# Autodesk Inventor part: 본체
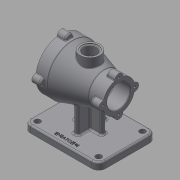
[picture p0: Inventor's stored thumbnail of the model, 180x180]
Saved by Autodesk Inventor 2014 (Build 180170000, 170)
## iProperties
Created: 2020-12
Part Number: 본체
Material: Generic
Document SubType Name: Modeling
Designer: kh
Density: 1 g/cm^3
Appearance: Default
Author: kh
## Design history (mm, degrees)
sketch "스케치1"
  geometry: L1 (-65, 50)-(65, 50); L2 (65, 50)-(65, -50); L3 (65, -50)-(-65, -50); L4 (-65, -50)-(-65, 50); L5 (-65, 50)-(65, -50); L6 (65, 50)-(-65, -50); 1 further point
  constraints: 12 end point, 2 midpoint, 2 parallel, 1 horizontal, 1 perpendicular
  dimensions: "d0" = 130 distance between parallel lines of L2 L4; "d1" = 100 distance between parallel lines of L3 L1
extrude "돌출1" new body sketch "스케치1" distance "d2" = 12; taper "d3" = 0 deg
sketch "스케치2"
  geometry: L1 (50, 82)-(-50, 82); L2 (-50, 82)-(-50, 109.5); L3 (-50, 109.5)-(-25, 109.5); L4 (-25, 109.5)-(30, 126); L5 (30, 126)-(50, 126); L6 (50, 126)-(50, 82); 2 further points
  constraints: 12 end point, 3 parallel, 1 horizontal, 1 midpoint, 1 perpendicular, 1 vertical alignment
  dimensions: "d4" = 82 distance from line of point (0, 0) L1; "d5" = 100 distance between parallel lines of L2 L6; "d6" = 55 diameter of L3 L1; "d7" = 88 diameter of L5 L1; "d8" = 20 distance of L4.end L5.end; "d119" = 25 distance of L2.end L3.end
revolve "회전1" sketch "스케치2" stored, may be unused: angle "d9" = 90 deg
sketch "스케치3"
  geometry: L1 (-24, 74.215)-(24, 74.215); L2 (24, 74.215)-(24, 0); L3 (24, 0)-(-24, 0); L4 (-24, 0)-(-24, 74.215); L5 (-24, 74.215)-(24, 0); L6 (24, 74.215)-(-24, 0); L7 (-65, 0)-(65, 0) reference; 4 further points
  constraints: 12 end point, 5 midpoint, 2 parallel, 1 horizontal, 1 perpendicular, 1 vertical alignment
  dimensions: "d10" = 48 distance between parallel lines of L2 L4
extrude "돌출2" join sketch "스케치3" stored distance "d11" = 8; taper "d12" = 0 deg
sketch "스케치4"
  geometry: L1 (-25, 90.309)-(25, 90.309); L2 (25, 90.309)-(25, 0); L3 (25, 0)-(-25, 0); L4 (-25, 0)-(-25, 90.309); 2 further points
  constraints: 8 end point, 2 parallel, 1 coincident, 1 horizontal, 1 midpoint, 1 perpendicular
  dimensions: "d120" = 50 distance between parallel lines of L4 L2
extrude "돌출3" join sketch "스케치4" stored distance "d14" = 8; taper "d15" = 0 deg
sketch "스케치5"
  geometry: C1 r 7 at (0, 44); 2 further points
  constraints: 2 vertical alignment, 1 centre point, 1 other
  dimensions: "d16" = 7 radius of C1
extrude "돌출4" join sketch "스케치5" distance "d17" = 15; taper "d18" = 0 deg
hole "구멍1" diameter "d21" = 4.134; stored, may be unused: countersink angle "d25" = 90 deg, drill point angle "d27" = 118 deg; dims "d19" = 10, "d20" = 10, "d22" = 9, "d23" = 4, "d24" = 2, "d26" = 11
sketch "스케치6"
  geometry: C1 r 7 at (0, 27.5); 2 further points
  constraints: 2 vertical alignment, 1 centre point, 1 other
  dimensions: "d32" = 7 radius of C1
extrude "돌출5" join sketch "스케치6" distance "d33" = 15; taper "d34" = 0 deg
hole "구멍2" diameter "d37" = 4.134; stored, may be unused: countersink angle "d41" = 90 deg, drill point angle "d43" = 118 deg; dims "d35" = 10, "d36" = 10, "d38" = 9, "d39" = 4, "d40" = 2, "d42" = 11
node "작업 평면1"
sketch "스케치7"
  geometry: C1 r 17 at (0, 0); 1 further point
  constraints: 1 centre point, 1 coincident
  dimensions: "d48" = 34 diameter of C1
extrude "돌출6" join sketch "스케치7" distance "d49" = 32.75; taper "d50" = 0 deg
sketch "스케치8"
  geometry: L1 (50, 82)-(-50, 82); L2 (-50, 82)-(-50, 102); L3 (-50, 102)-(-20, 102); L4 (-20, 102)-(-20, 108); L5 (-20, 108)-(27, 108); L6 (27, 108)-(27, 114); L7 (27, 114)-(50, 114); L8 (50, 114)-(50, 82); L9 (50, 88.978)-(50, 125.443) reference; L10 (50, 89)-(50, 75) reference; L11 (50, 38.557)-(50, 75.022) reference; L12 (-50, 88.943)-(-50, 108.609) reference; L13 (-50, 55.391)-(-50, 75.057) reference; L14 (-50, 79.933)-(-50, 84.067) reference; L15 (-50, 75)-(-50, 89) reference; L16 (50, 133)-(50, 125.443) reference; L17 (50, 38.557)-(35, 38.557) reference; L18 (50, 38.557)-(50, 38.557) reference; L19 (35, 38.557)-(50, 38.557) reference; L20 (35, 38.557)-(35, 38.557) reference; L21 (50, 38.557)-(50, 31) reference; 2 further points
  constraints: 16 end point, 4 parallel, 2 vertical, 1 horizontal, 1 midpoint, 1 perpendicular, 1 point on line
  dimensions: "d51" = 82 distance from line of point (0, 0) L1; "d52" = 64 diameter of L7 L1; "d53" = 52 diameter of L5 L1; "d54" = 40 diameter of L3 L1; "d55" = 100 distance from line of L2 L10.start; "d56" = 23 distance between parallel lines of L6 L8; "d57" = 30 distance between parallel lines of L2 L4
revolve "회전2" sketch "스케치8" stored, may be unused: angle "d58" = 90 deg
hole "구멍3" diameter "d61" = 28; stored, may be unused: countersink angle "d65" = 90 deg, drill point angle "d67" = 0 deg; dims "d59" = 10, "d60" = 10, "d62" = 9, "d63" = 4, "d64" = 2, "d66" = 1
hole "구멍4" diameter "d70" = 22; stored, may be unused: countersink angle "d74" = 90 deg, drill point angle "d76" = 0 deg; dims "d68" = 10, "d69" = 10, "d71" = 9, "d72" = 4, "d73" = 2, "d75" = 33.25
fillet "모깎기1" dims "d77" = 12
hole "구멍5" diameter "d80" = 10; stored, may be unused: countersink angle "d84" = 90 deg, drill point angle "d86" = 0 deg; dims "d78" = 10, "d79" = 10, "d81" = 9, "d82" = 4, "d83" = 2, "d85" = 33.25
fillet "모깎기2" dims "d91" = 3
fillet "모깎기7" dims "d96" = 3
chamfer "모따기1" distance "d98" = 1; stored, may be unused: second distance "d99" = 2, angle "d100" = 45 deg
fillet "모깎기9" dims "d101" = 3
fillet "모깎기10" dims "d102" = 3
chamfer "모따기2" distance "d103" = 1; stored, may be unused: second distance "d104" = 2, angle "d105" = 45 deg
fillet "모깎기13" dims "d108" = 3
fillet "모깎기14" dims "d109" = 3
fillet "모깎기15" dims "d110" = 1
fillet "모깎기16" dims "d111" = 1
fillet "모깎기18" dims "d113" = 1
sketch "스케치9"
  geometry: L1 (-53, -50)-(53, -50) reference; 2 further points
  constraints: 1 vertical alignment, 1 other
  dimensions: "d114" = 10 distance from line of L1 point (0, -40)
feature "엠보싱1" sketch "스케치9" dims "d10" = 48, "d115" = 0.5, "d116" = 0
fillet "모깎기20" dims "d122" = 3
fillet "모깎기21" dims "d123" = 3
fillet "모깎기22" dims "d124" = 3
node "솔리드1"
pattern_circular "원형 패턴1" dims angle "d29" = 360 deg
pattern_circular "원형 패턴2" dims angle "d45" = 360 deg
pattern_linear "직사각형 패턴1"
node "투영된 루프1"
other parameters: "d47" = -127
